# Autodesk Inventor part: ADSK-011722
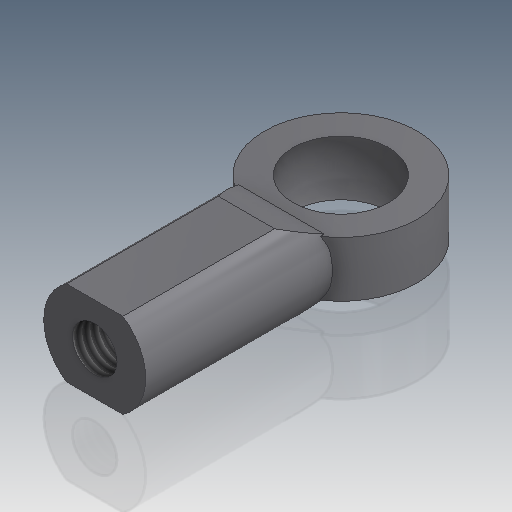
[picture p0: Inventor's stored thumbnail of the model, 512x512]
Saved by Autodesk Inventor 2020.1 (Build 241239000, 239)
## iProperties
Created: 1999-12
Part Number: ADSK-011722
Material: Acier (alliage faible hypertrempé)
Document SubType Name: Modeling
Designer: gpurviance
Density: 7.84 g/cm^3
Appearance: Metal-Steel(Polish)
Mass: 81.8067 g
Surface Area: 51.4254 cm^2
Volume: 10.4345 cm^3
Control State: 0
Checked Out: False
Last Check In By: gpurviance
Last Check In Date: 1999-12-17
Master: False
Shininess: 0.0
Length Units: 11272
Angle Units: 11279
Time Units: 11290
Mass Units: 11286
Length Display Precision: 3
Angle Display Precision: 2
Compacted: True
Dimensions: 0,6x2,4x1,1 in
Mass: 0,18 lb
DocNumber: ADSK-011722.ipt
Folder: 01 - Themengebiete\Simplification\01 - Packaging machine\
VDS_Category: 3D Komponenten
VLT_Material: Acier (alliage faible hypertrempé)
Density: 0.0
Volumn: 0.0
Area: 0.0
PropertySet Name: Model Information
Author: gpurviance
Revision Number: -
Title: standard part
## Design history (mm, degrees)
node "Extrusion1" dims "d4" = 34.925, "d5" = 0
workplane "Work Plane1"
node "Revolution1" dims "d11" = 90 deg
node "Hole1" dims "d12" = 8.376, "d13" = 9.525, "d14" = 6.35, "d15" = 60 deg, "d16" = 27.2796, "d17" = 118 deg, "d21" = 19.9898
  sketch "Sketch4"
    geometry: A1 r 9.525 centre (0, 0) between (-5.265, 7.938) and (-5.265, -7.938) reference; 1 further point
    constraints: 1 coincident
node "Extrusion2" dims "d19" = 31.75, "d20" = 0
node "Solide1"
node "Corps solides"
node "Corps surfaciques"
sketch "Sketch1"
  geometry: L1 (-9.525, 7.938)-(11.112, 7.938); L2 (11.112, -7.937)-(-9.525, -7.938); A1 r 9.525 centre (0, 0) between (5.265, -7.937) and (5.265, 7.938); A2 r 9.525 centre (0, 0) between (-5.265, 7.938) and (-5.265, -7.938)
  constraints: 4 end point, 4 point on circle, 4 point on line, 2 centre point, 1 concentric, 1 horizontal, 1 parallel, 1 other
  dimensions: "d1" = 7.9375 distance from line of A1.centre L2 (= 0.5 x d2); "d2" = 15.875 distance between parallel lines of L1 L2; "d3" = 9.525 radius of A1
sketch "Sketch3"
  geometry: L1 (-5.265, 7.938)-(5.265, 7.938) reference; L2 (5.265, -7.938)-(-5.265, -7.937) reference; L3 (0, -7.938)-(0, 7.938); L4 (0, 0)-(-6.35, 0); L5 (-14.288, 5.159)-(-14.287, -5.159); L6 (-14.287, -5.159)-(-8.936, -5.159); L7 (-14.288, 5.159)-(-8.936, 5.159); A1 r 10.319 centre (0, 0) between (-8.936, 5.159) and (-8.936, -5.159)
  constraints: 10 end point, 3 midpoint, 2 perpendicular, 2 point on circle, 1 centre point, 1 coincident
  dimensions: "d7" = 10.31875 radius of A1; "d8" = 14.2875 distance between parallel lines of L3 L5; "d9" = 10.31875 distance between parallel lines of L7 L6; "d10" = 5.15938 distance between parallel lines of L6 L4 (= 0.5 x d9)
sketch "Sketch6"
  geometry: L1 (5.159, -25.4)-(5.159, 0.721) reference; L2 (-5.159, -25.4)-(-5.159, 0.721) reference; L3 (7.938, 0)-(7.938, 34.925) reference; L4 (-7.938, 0)-(-7.938, 34.925) reference; L5 (7.938, 6.55)-(5.159, 0); L6 (-5.159, 0)-(-7.938, 6.458); L7 (7.938, 6.55)-(16.052, 6.55); L8 (16.052, 6.55)-(16.052, -2.399); L9 (16.052, -2.399)-(7.938, -2.399); L10 (7.938, -2.399)-(5.159, 0); L11 (-5.159, 0)-(-8.118, -2.399); L12 (-8.118, -2.399)-(-15.775, -2.399); L13 (-15.775, -2.399)-(-15.775, 6.458); L14 (-15.775, 6.458)-(-7.938, 6.458)
  constraints: 20 end point, 4 point on line, 3 perpendicular, 2 parallel, 1 collinear
other parameters: "d0" = 19.05, "d6" = 11.1125
